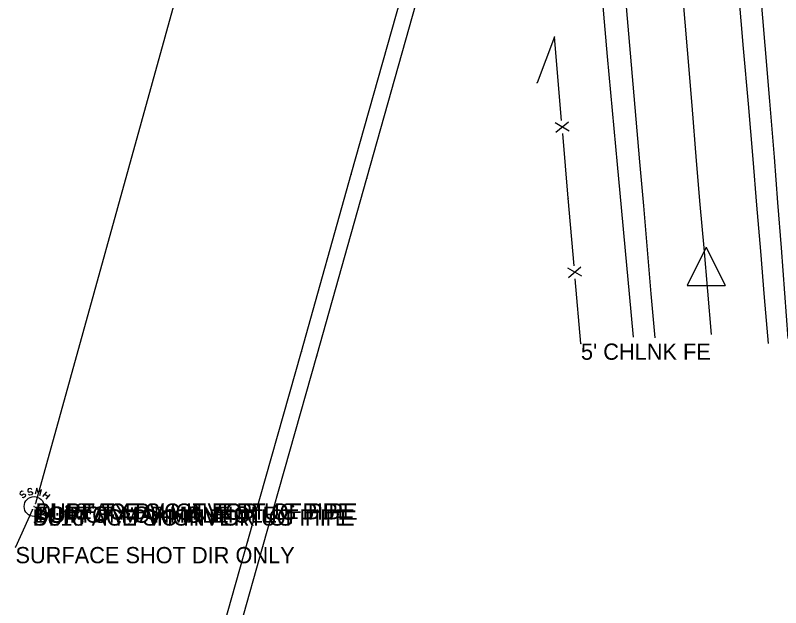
# Model space of a CAD drawing. Extents: x 929765 to 934279, y 1533086 to 1541189.
# Drawn here: x 931827.8 to 932063, y 1536953.2 to 1537135.2 of the extents above; entities that cross this region are included whole.
import ezdxf

# ---------------------------------------------------------------- set-up
doc = ezdxf.new("R2010")
doc.units = 0
for name, color, linetype in [('S_CAL_CORNER', 7, 'Continuous'), ('S_EDGE_PAVEMENT', 7, 'Continuous'), ('S_FENCE', 7, 'Continuous'), ('S_FENCE_ANNOT', 7, 'Continuous'), ('S_MANHOLE_ANNOT', 7, 'Continuous'), ('S_MSC_PT_SYM', 7, 'Continuous'), ('S_PAVEMENT_CROWN', 7, 'Continuous'), ('S_RAILROAD', 7, 'Continuous'), ('S_SANITARY_SEWER', 7, 'Continuous'), ('S_SANITARY_SEWER_ANNOT', 7, 'Continuous'), ('S_SHOULDER', 7, 'Continuous'), ('S_SURVEY_TEXT_ANNOT', 7, 'Continuous'), ('S_UTL_PT_SYM', 7, 'Continuous')]:
    doc.layers.add(name, color=color, linetype=linetype)

msp = doc.modelspace()

# ---------------------------------------------------------------- linework, layer by layer
at = {"layer": 'S_CAL_CORNER'}
for p, q in [((932040.15, 1537063.98), (932034.28, 1537052.16)), ((932040.15, 1537063.98), (932034.28, 1537052.16)), ((932040.15, 1537063.98), (932045.97, 1537052.16)), ((932040.15, 1537063.98), (932045.97, 1537052.16)), ((932034.28, 1537052.16), (932045.97, 1537052.16)), ((932034.28, 1537052.16), (932045.97, 1537052.16))]:
    msp.add_line(p, q, dxfattribs=at)
at = {"layer": 'S_EDGE_PAVEMENT'}
for points in [[(932059.21, 1537034.36), (932058.05, 1537048.52), (932056.89, 1537062.69), (932055.72, 1537076.85), (932054.56, 1537091.01), (932053.08, 1537108.03), (932051.6, 1537125.05), (932050.12, 1537142.07), (932048.64, 1537159.08), (932046.94, 1537178.95), (932045.24, 1537198.83), (932043.54, 1537218.7), (932041.84, 1537238.57), (932040.71, 1537252.26), (932039.58, 1537265.94), (932038.44, 1537279.63), (932037.31, 1537293.31), (932035.21, 1537317.83), (932033.1, 1537342.36), (932031.84, 1537358.72), (932030.59, 1537375.09), (932029.34, 1537391.46), (932028.08, 1537407.83)], [(932024.4, 1537036.12), (932023.24, 1537049.63), (932022.08, 1537063.14), (932020.92, 1537076.65), (932019.76, 1537090.16), (932018.3, 1537106.87), (932016.84, 1537123.59), (932015.38, 1537140.3), (932013.92, 1537157.01), (932012.23, 1537176.89), (932010.54, 1537196.76), (932008.86, 1537216.64), (932007.17, 1537236.51), (932005.86, 1537251.22), (932004.55, 1537265.93), (932003.24, 1537280.64), (932001.93, 1537295.34), (932000.68, 1537312.96)]]:
    msp.add_lwpolyline(points, dxfattribs=at)
at = {"layer": 'S_FENCE'}
for p, q in [((931998.02, 1537099.64), (931993.7, 1537102.15)), ((931998.02, 1537099.64), (931993.7, 1537102.15)), ((931993.94, 1537099.29), (931997.78, 1537102.5)), ((931993.94, 1537099.29), (931997.78, 1537102.5)), ((932001.88, 1537055), (931997.55, 1537057.5)), ((932001.88, 1537055), (931997.55, 1537057.5)), ((931997.8, 1537054.65), (932001.63, 1537057.86)), ((931997.8, 1537054.65), (932001.63, 1537057.86))]:
    msp.add_line(p, q, dxfattribs=at)
for points in [[(931993.5, 1537128.55), (931988.14, 1537114.46)], [(931993.5, 1537128.55), (931988.14, 1537114.46)], [(931995.69, 1537102.89), (931993.5, 1537128.55)], [(931995.69, 1537102.89), (931993.5, 1537128.55)], [(931997.73, 1537078.98), (931996.03, 1537098.9)], [(931997.73, 1537078.98), (931996.03, 1537098.9)], [(931999.54, 1537058.25), (931997.73, 1537078.98)], [(931999.54, 1537058.25), (931997.73, 1537078.98)], [(932001.62, 1537034.34), (931999.89, 1537054.26)], [(932001.62, 1537034.34), (931999.89, 1537054.26)]]:
    msp.add_lwpolyline(points, dxfattribs=at)
at = {"layer": 'S_MSC_PT_SYM'}
for points in [[(931993.5, 1537128.55), (931993.5, 1537128.6), (931993.5, 1537128.55), (931993.45, 1537128.55), (931993.5, 1537128.55), (931993.5, 1537128.5), (931993.5, 1537128.55), (931993.55, 1537128.55)], [(931988.14, 1537114.46), (931988.14, 1537114.51), (931988.14, 1537114.46), (931988.09, 1537114.46), (931988.14, 1537114.46), (931988.14, 1537114.41), (931988.14, 1537114.46), (931988.19, 1537114.46)], [(931931.04, 1537086.37), (931931.04, 1537086.42), (931931.04, 1537086.37), (931930.99, 1537086.37), (931931.04, 1537086.37), (931931.04, 1537086.32), (931931.04, 1537086.37), (931931.09, 1537086.37)], [(931935.87, 1537085.13), (931935.87, 1537085.18), (931935.87, 1537085.13), (931935.82, 1537085.13), (931935.87, 1537085.13), (931935.87, 1537085.08), (931935.87, 1537085.13), (931935.92, 1537085.13)], [(931997.73, 1537078.98), (931997.73, 1537079.03), (931997.73, 1537078.98), (931997.68, 1537078.98), (931997.73, 1537078.98), (931997.73, 1537078.93), (931997.73, 1537078.98), (931997.78, 1537078.98)], [(932001.62, 1537034.34), (932001.62, 1537034.39), (932001.62, 1537034.34), (932001.57, 1537034.34), (932001.62, 1537034.34), (932001.62, 1537034.29), (932001.62, 1537034.34), (932001.67, 1537034.34)], [(931915.76, 1537031.85), (931915.76, 1537031.9), (931915.76, 1537031.85), (931915.71, 1537031.85), (931915.76, 1537031.85), (931915.76, 1537031.8), (931915.76, 1537031.85), (931915.81, 1537031.85)], [(931920.44, 1537030.54), (931920.44, 1537030.59), (931920.44, 1537030.54), (931920.39, 1537030.54), (931920.44, 1537030.54), (931920.44, 1537030.49), (931920.44, 1537030.54), (931920.49, 1537030.54)], [(931833.98, 1536985.2), (931833.98, 1536985.25), (931833.98, 1536985.2), (931833.93, 1536985.2), (931833.98, 1536985.2), (931833.98, 1536985.15), (931833.98, 1536985.2), (931834.03, 1536985.2)], [(931833.08, 1536983.38), (931833.08, 1536983.43), (931833.08, 1536983.38), (931833.03, 1536983.38), (931833.08, 1536983.38), (931833.08, 1536983.33), (931833.08, 1536983.38), (931833.13, 1536983.38)], [(931899.27, 1536973.69), (931899.27, 1536973.74), (931899.27, 1536973.69), (931899.22, 1536973.69), (931899.27, 1536973.69), (931899.27, 1536973.64), (931899.27, 1536973.69), (931899.32, 1536973.69)], [(931903.88, 1536971.99), (931903.88, 1536972.04), (931903.88, 1536971.99), (931903.83, 1536971.99), (931903.88, 1536971.99), (931903.88, 1536971.94), (931903.88, 1536971.99), (931903.93, 1536971.99)]]:
    msp.add_lwpolyline(points, dxfattribs=at)
at = {"layer": 'S_PAVEMENT_CROWN'}
msp.add_lwpolyline([(932041.76, 1537037.1), (932040.61, 1537050.43), (932039.45, 1537063.77), (932038.3, 1537077.1), (932037.14, 1537090.44), (932035.75, 1537107.51), (932034.36, 1537124.59), (932032.97, 1537141.66), (932031.58, 1537158.74), (932029.79, 1537178.36), (932027.99, 1537197.98), (932026.19, 1537217.6), (932024.39, 1537237.22), (932023.31, 1537251.24), (932022.23, 1537265.26), (932021.15, 1537279.28), (932020.07, 1537293.3), (932019.35, 1537306.62), (932018.64, 1537319.95), (932017.92, 1537333.27), (932017.2, 1537346.6), (932015.42, 1537361.67)], dxfattribs=at)
at = {"layer": 'S_RAILROAD'}
for p, q in [((931931.04, 1537086.37), (931946.32, 1537140.45)), ((931935.87, 1537085.13), (931950.98, 1537138.91)), ((931915.76, 1537031.85), (931931.04, 1537086.37)), ((931920.44, 1537030.54), (931935.87, 1537085.13)), ((931899.27, 1536973.69), (931915.76, 1537031.85)), ((931903.88, 1536971.99), (931920.44, 1537030.54)), ((931884, 1536919.75), (931899.27, 1536973.69)), ((931888.87, 1536918.86), (931903.88, 1536971.99))]:
    msp.add_line(p, q, dxfattribs=at)
at = {"layer": 'S_SANITARY_SEWER'}
for p, q in [((931919.02, 1537291.78), (931833.98, 1536985.2)), ((931829.24, 1536988.56), (931829.17, 1536988.17)), ((931829.17, 1536988.17), (931829.36, 1536987.9)), ((931829.79, 1536988.94), (931829.24, 1536988.56)), ((931829.36, 1536987.9), (931829.79, 1536987.78)), ((931830.21, 1536988.87), (931829.79, 1536988.94)), ((931829.79, 1536987.78), (931830.33, 1536988.13)), ((931830.33, 1536988.13), (931830.79, 1536988.05)), ((931830.79, 1536988.05), (931830.95, 1536987.78)), ((931830.95, 1536987.78), (931830.87, 1536987.35)), ((931836.22, 1536987.32), (931837.46, 1536988.79)), ((931836.88, 1536988.09), (931837.85, 1536987.28)), ((931838.43, 1536987.97), (931837.19, 1536986.5)), ((931830.33, 1536986.97), (931829.94, 1536987.04)), ((931830.87, 1536987.35), (931830.33, 1536986.97)), ((931833.08, 1536983.38), (931827.84, 1536971.81))]:
    msp.add_line(p, q, dxfattribs=at)
for points in [[(931835.33, 1536987.63), (931835.87, 1536989.49), (931834.82, 1536988.48), (931834.44, 1536989.91), (931833.89, 1536988.05)], [(931832.89, 1536989.49), (931832.54, 1536989.76), (931831.88, 1536989.68), (931831.65, 1536989.33), (931831.68, 1536989.02), (931832.03, 1536988.71), (931832.65, 1536988.83), (931833.04, 1536988.52), (931833.08, 1536988.21), (931832.81, 1536987.82), (931832.19, 1536987.74), (931831.84, 1536988.01)]]:
    msp.add_lwpolyline(points, dxfattribs=at)
msp.add_circle((931833.57, 1536984.25), 3.05, dxfattribs=at)
at = {"layer": 'S_SHOULDER'}
for points in [[(932065.34, 1537035.86), (932064.27, 1537049.8), (932063.21, 1537063.74), (932062.14, 1537077.68), (932061.08, 1537091.63), (932059.66, 1537108.77), (932058.23, 1537125.91), (932056.81, 1537143.06), (932055.39, 1537160.2), (932053.73, 1537179.84), (932052.07, 1537199.48), (932050.41, 1537219.11), (932048.75, 1537238.75), (932047.67, 1537252.72), (932046.6, 1537266.7), (932045.52, 1537280.67), (932044.45, 1537294.64), (932042.28, 1537319.47), (932040.11, 1537344.3), (932038.43, 1537365.02), (932036.75, 1537385.74), (932035.07, 1537406.47), (932033.39, 1537427.19)], [(932017.74, 1537036.33), (932016.51, 1537049.59), (932015.29, 1537062.86), (932014.07, 1537076.12), (932012.85, 1537089.38), (932011.34, 1537105.97), (932009.83, 1537122.57), (932008.33, 1537139.16), (932006.82, 1537155.75), (932005.16, 1537175.6), (932003.5, 1537195.45), (932001.85, 1537215.3), (932000.19, 1537235.14), (931999.04, 1537249.92), (931997.89, 1537264.69), (931996.74, 1537279.47), (931995.59, 1537294.25)]]:
    msp.add_lwpolyline(points, dxfattribs=at)
at = {"layer": 'S_UTL_PT_SYM'}
for points in [[(931833.98, 1536985.2), (931833.98, 1536985.25), (931833.98, 1536985.2), (931833.93, 1536985.2), (931833.98, 1536985.2), (931833.98, 1536985.15), (931833.98, 1536985.2), (931834.03, 1536985.2)], [(931833.08, 1536983.38), (931833.08, 1536983.43), (931833.08, 1536983.38), (931833.03, 1536983.38), (931833.08, 1536983.38), (931833.08, 1536983.33), (931833.08, 1536983.38), (931833.13, 1536983.38)], [(931833.57, 1536984.25), (931833.57, 1536984.3), (931833.57, 1536984.25), (931833.52, 1536984.25), (931833.57, 1536984.25), (931833.57, 1536984.2), (931833.57, 1536984.25), (931833.62, 1536984.25)], [(931827.84, 1536971.81), (931827.84, 1536971.86), (931827.84, 1536971.81), (931827.79, 1536971.81), (931827.84, 1536971.81), (931827.84, 1536971.76), (931827.84, 1536971.81), (931827.89, 1536971.81)]]:
    msp.add_lwpolyline(points, dxfattribs=at)

# ---------------------------------------------------------------- texts
at = {"layer": 'S_FENCE_ANNOT'}
msp.add_text("5' CHLNK FE", height=5, dxfattribs=at).set_placement((932001.62, 1537029.34))
at = {"layer": 'S_MANHOLE_ANNOT'}
msp.add_text('BOTTOM OF MANHOLE', height=5, dxfattribs=at).set_placement((931833.57, 1536979.25))
at = {"layer": 'S_SANITARY_SEWER_ANNOT'}
for s, p in [('DI:18" TY:PVC INVERT OF PIPE', (931833.98, 1536980.2)), ('DI:18" TY:PVC INVERT OF PIPE', (931833.08, 1536978.38)), ('TOP OF MANHOLE', (931833.57, 1536979.25)), ('SURFACE SHOT DIR ONLY', (931827.84, 1536966.81))]:
    msp.add_text(s, height=5, dxfattribs=at).set_placement(p)
at = {"layer": 'S_SURVEY_TEXT_ANNOT'}
for p in [(931833.98, 1536980.2), (931833.08, 1536978.38)]:
    msp.add_text('SURFACE SHOT FOR UG PIPE', height=5, dxfattribs=at).set_placement(p)

doc.saveas('drawing.dxf')
